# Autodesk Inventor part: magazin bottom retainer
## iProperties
Created: 2006-04
Part Number: magazin bottom retainer
Document SubType Name: Modeling
Designer: Калинин
Author: Калинин
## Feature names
1. Выдавливание1 [Extrusion]
2. Выдавливание2 [Extrusion]
3. Выдавливание3 [Extrusion]
4. Выдавливание4 [Extrusion]
5. Выдавливание5 [Extrusion]
6. Сопряжение1 [Fillet]
7. Сопряжение2 [Fillet]
8. Сопряжение3 [Fillet]
9. Сопряжение4 [Fillet]
10. Сопряжение5 [Fillet]
11. Сопряжение6 [Fillet]
12. Выдавливание6 [Extrusion]
13. Вращение1 [Revolution]
14. Выдавливание7 [Extrusion]
15. Вращение2 [Revolution]
16. Выдавливание8 [Extrusion]
17. Выдавливание9 [Extrusion]
18. Сопряжение7 [Fillet]
